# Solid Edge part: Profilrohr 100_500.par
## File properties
Username: ahadarics
Dokumentum tartalom típus: 0
Author: ahadarics
Last saved by: ahadarics
Revision: 88
Sűrűség: 0,000 kg/m^3
Pontosság: 0,990
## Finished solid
Body 1: solid body, 179 faces, 530 edges, 352 vertices.
  Faces by surface: cylinder 109, plane 70
  Edges by curve: line 312, circle 218
Bounding box of the edges (mm): 105.500 x 105.500 x 557.000, from (-52.75, -52.75, -516) to (52.75, 52.75, 41).
Cylindrical faces by radius (mm): R0.1 x16, R0.2 x30, R0.5 x28, R1 x10, R4.6 x8, R5.7 x4, R7.5 x4, R50 x1, R52.7 x8
Planar faces by outward normal: +x 6, +y 6, +z 1, -x 4, -y 4, -z 1, oblique 48
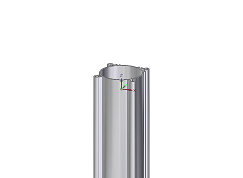
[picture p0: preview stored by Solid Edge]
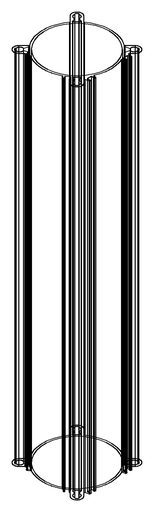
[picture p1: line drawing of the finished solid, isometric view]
